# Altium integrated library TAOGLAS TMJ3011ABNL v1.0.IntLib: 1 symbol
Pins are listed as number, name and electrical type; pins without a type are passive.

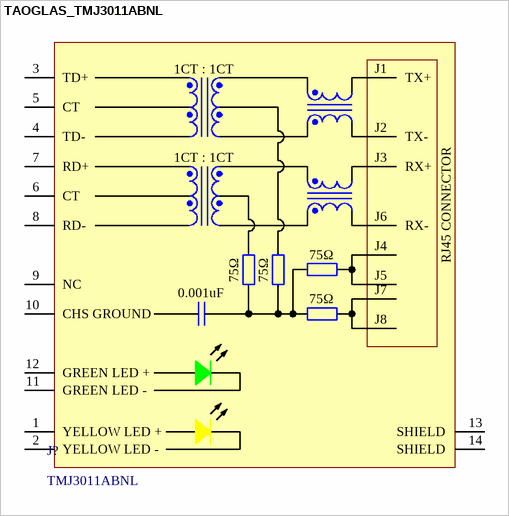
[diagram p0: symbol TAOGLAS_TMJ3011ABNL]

## TAOGLAS_TMJ3011ABNL
designator J?, comment TMJ3011ABNL
RJ45 connector with integrated magnetics 10/100Base-T Single Port Tab-UP with SMT mount and LEDs; ComponentLibStatus: Created; MFG: Taoglas; Temp_High: +85C; Temp_Low: -40C
footprint TAOGLAS_TMJ3011ABNL (RJ45 connector with integrated magnetics 10/100Base-T Single Port Tab-UP with SMT mount and LEDs)
pins: 1 YELLOW LED +, 2 YELLOW LED -, 3 TD+, 4 TD-, 5 CT, 6 CT, 7 RD+, 8 RD-, 9 NC, 10 CHS GROUND, 11 GREEN LED -, 12 GREEN LED +, 13 SHIELD, 14 SHIELD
